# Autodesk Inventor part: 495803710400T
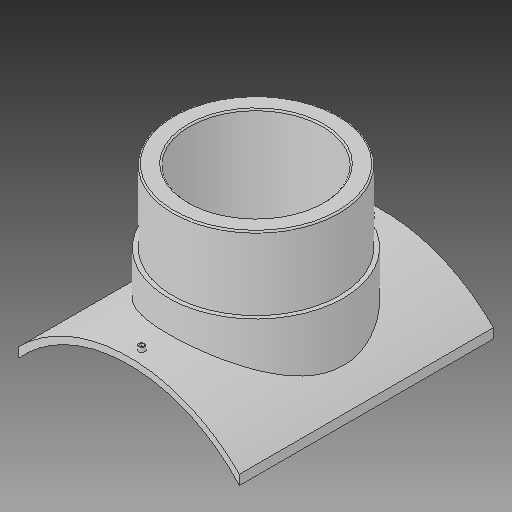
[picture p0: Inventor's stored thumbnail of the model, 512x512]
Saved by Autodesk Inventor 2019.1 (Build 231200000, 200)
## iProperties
Created: 2017-10
Part Number: 495803710400T
Material: Generic
Description: PLASSON BRANCH SADDLE  710x400
Document SubType Name: Modeling
Designer: KIM
Mass: 2754.05 g
Surface Area: 3037.44 cm^2
Volume: 2754.05 cm^3
Density: 1 g/cm^3
Appearance: Default
Author: KIM
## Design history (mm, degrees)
derived "495803.ipt"
feature "Solid1::495803.ipt"
tag "TaggingFeature1"
body "Solid1"
other parameters: "d1" = 16, "d4" = 0, "d12" = 380.6, "d13" = 14, "d14" = 274.5, "d16" = 5 deg, "d18" = 4, "d19" = 14, "d20" = 0, "d21" = 3, "d22" = 0, "d23" = 621, "d25" = 16, "d28" = 0, "d29" = 9.6, "d31" = 0, "d32" = 125, "d33" = 0, "d34" = 7.1, "d37" = 175, "d38" = 0, "d39" = 3.55, "x_" = 16, "D_" = 16
